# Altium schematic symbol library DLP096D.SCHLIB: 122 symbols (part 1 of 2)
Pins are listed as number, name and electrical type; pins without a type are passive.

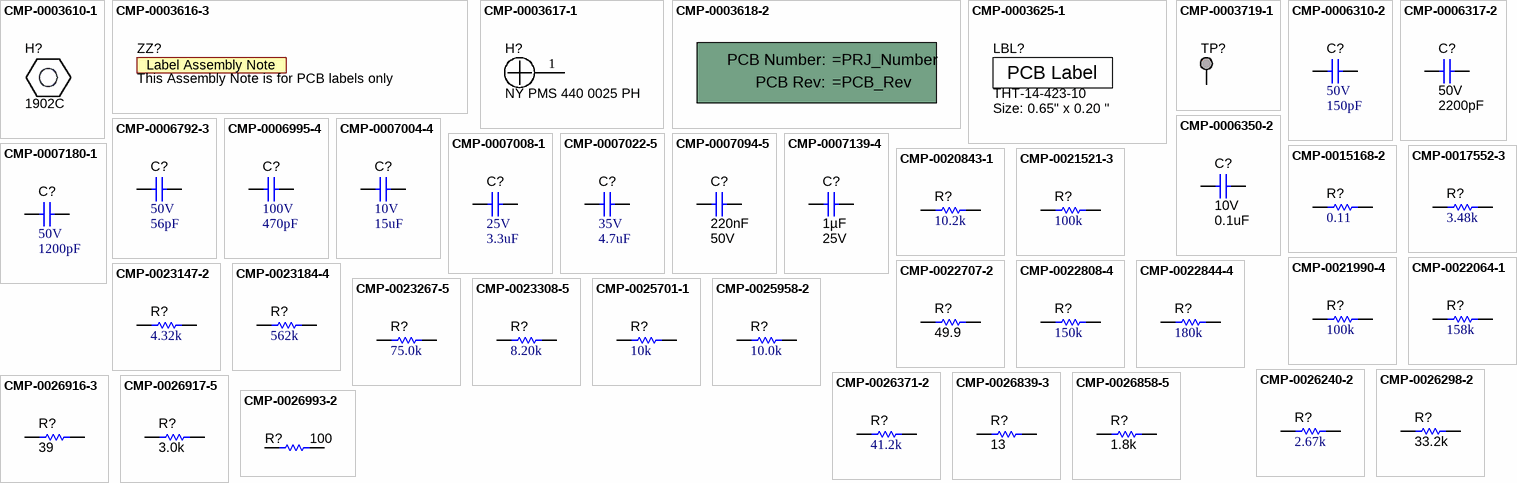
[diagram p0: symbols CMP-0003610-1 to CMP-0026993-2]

## CMP-0003610-1
designator H?, comment 1902C
Standoff, Hex, 0.5"L #4-40 Nylon; Manufacturer: Keystone; CompType: Hardware
footprint Keystone_1902C (Hex Standoff, 4-40 threaded, nylon)

## CMP-0003616-3
designator ZZ?, comment This Assembly Note is for PCB labels only  (no BOM)
Key: AssemblyNoteLabel
footprint AssemblyNoteLabel (Assembly Note for PCB Labels)

## CMP-0003617-1
designator H?, comment NY PMS 440 0025 PH
Machine Screw, Round, #4-40 x 1/4, Nylon, Philips panhead; Manufacturer: B&F Fastener Supply; CompType: Hardware
footprint NY PMS 440 0025 PH (4-40 nylon screw and mounting hole)
footprint NY PMS 440 0025 PH_3Donly (4-40 nylon screw)
pins: 1

## CMP-0003618-2
designator !PCB?, comment Printed Circuit Board  (value not drawn)  (mechanical)
Manufacturer: Any; CompType: PCB
1 alternate drawing of the same symbol

## CMP-0003625-1
designator LBL?, comment THT-14-423-10  Note: Size: 0.65" x 0.20 "
Thermal Transfer Printable Labels, 0.650" W x 0.200" H - 10,000 per roll; Manufacturer: Brady; CompType: Label
footprint Label_650x200 (Thermal Transfer Label)

## CMP-0003719-1
designator TP?, comment TP_H0.45P0.75  (value not drawn)  (no BOM)
Testpoint; Manufacturer: Texas Instruments; CompType: Pad
footprint TP_H045P075 (TP_H0.45P0.75)
pins: 1

## CMP-0006310-2
designator C?, comment VDC_V: 50V  ValueDisplayed: 150pF  (hidden comment: CGA2B2C0G1H151J050BA)
CAP, CERM, 150 pF, 50 V, +/- 5%, C0G/NP0, AEC-Q200 Grade 1, 0402; Manufacturer: TDK; TaMin_C: -55°C; Polarized: N; SizeAreaWB_mm2: 3; Value1: Unknown; U/M: EA; Value: 150pF; TaMax_C: 125°C; SizeZ_mm: 0.6; SizeX_mm: 1; SizeY_mm: 0.5; Cap_Case: 0402; CompType: Capacitor; AEC Qualified: Y; AEC Category: Q200
footprint 0402 (0402 from SM-752 data)
footprint 0402S (Based on C0402S footprint from PADS legacy)
footprint 0402L (0402 from SM-752 data)
footprint 0402M (0402 from SM-752 data)
pins: 1, 2

## CMP-0006317-2
designator C?, comment VDC_V: 50V  ValueDisplayed: 2200pF  (hidden comment: CGA2B2X7R1H222K050BA)
CAP, CERM, 2200 pF, 50 V, +/- 10%, X7R, AEC-Q200 Grade 1, 0402; Manufacturer: TDK; TaMin_C: -55°C; ESR_ohm: 1.07794; Polarized: N; SizeAreaWB_mm2: 3; Value1: 1.07794 ohm; U/M: EA; Value: 2200pF; TaMax_C: 125°C; SizeZ_mm: 0.6; SizeX_mm: 1; SizeY_mm: 0.5; Cap_Case: 0402; CompType: Capacitor; AEC Qualified: Y; Cap_F: 2.2nF; IRMS_A: 264.071mA; AEC Category: Q200
footprint 0402 (0402 from SM-752 data)
footprint 0402S (Based on C0402S footprint from PADS legacy)
footprint 0402L (0402 from SM-752 data)
footprint 0402M (0402 from SM-752 data)
pins: 1, 2

## CMP-0006350-2
designator C?, comment VDC_V: 10V  ValueDisplayed: 0.1uF  (hidden comment: GCM155R71A104KA55D)
CAP, CERM, 0.1 uF, 10 V, +/- 10%, X7R, AEC-Q200 Grade 1, 0402; Manufacturer: MuRata; TaMin_C: -55°C; Polarized: N; SizeAreaWB_mm2: 3; Value1: Unknown; U/M: EA; Value: 0.1uF; TaMax_C: 125°C; SizeZ_mm: 0.6; SizeX_mm: 1; SizeY_mm: 0.5; Cap_Case: 0402; CompType: Capacitor; AEC Qualified: Y; Cap_F: 100nF; AEC Category: Q200
footprint 0402 (0402 from SM-752 data)
footprint 0402S (Based on C0402S footprint from PADS legacy)
footprint 0402L (0402 from SM-752 data)
footprint 0402M (0402 from SM-752 data)
pins: 1, 2

## CMP-0006792-3
designator C?, comment VDC_V: 50V  ValueDisplayed: 56pF  (hidden comment: 06035A560FAT2A)
CAP, CERM, 56 pF, 50 V, +/- 1%, C0G/NP0, 0603; Manufacturer: AVX; TaMin_C: -55°C; Polarized: N; SizeAreaWB_mm2: 4.68; Value1: Unknown; U/M: EA; Value: 56pF; TaMax_C: 125°C; SizeZ_mm: 1; SizeX_mm: 1.6; SizeY_mm: 0.8; Cap_Case: 0603; SizeArea_mm2: 1.28; CompType: Capacitor; AEC Category: Q200
footprint 0603 (0603 from SM-752 data)
footprint 0603_HV (Ernesto recommended land pattern.  26 mil between pads.)
footprint 0603L (0603 from SM-752 data)
footprint 0603S
footprint 0603M (0603 from SM-752 data)
pins: 1, 2

## CMP-0006995-4
designator C?, comment VDC_V: 100V  ValueDisplayed: 470pF  (hidden comment: C1608C0G2A471J)
CAP, CERM, 470 pF, 100 V, +/- 5%, C0G/NP0, 0603; Manufacturer: TDK; TaMin_C: -55°C; ESR_ohm: 71.4m; Polarized: N; SizeAreaWB_mm2: 4.68; Value1: 0.0714 ohm; U/M: EA; Value: 470pF; TaMax_C: 125°C; SizeZ_mm: 1; SizeX_mm: 1.6; SizeY_mm: 0.8; Cap_Case: 0603; SizeArea_mm2: 1.28; CompType: Capacitor; AEC Category: Q200
footprint 0603 (0603 from SM-752 data)
footprint 0603_HV (Ernesto recommended land pattern.  26 mil between pads.)
footprint 0603L (0603 from SM-752 data)
footprint 0603S
footprint 0603M (0603 from SM-752 data)
pins: 1, 2

## CMP-0007004-4
designator C?, comment VDC_V: 10V  ValueDisplayed: 15uF  (hidden comment: C1608X5R1A156M080AC)
CAP, CERM, 15 uF, 10 V, +/- 20%, X5R, 0603; Manufacturer: TDK; TaMin_C: -55°C; ESR_ohm: 6.531m; Polarized: N; SizeAreaWB_mm2: 4.68; Value1: 0.006531 ohm; U/M: EA; Value: 15uF; TaMax_C: 85°C; SizeZ_mm: 1; SizeX_mm: 1.6; SizeY_mm: 0.8; Cap_Case: 0603; SizeArea_mm2: 1.28; CompType: Capacitor; Cap_F: 15µF; IRMS_A: 2.0344A; AEC Category: Q200
footprint 0603 (0603 from SM-752 data)
footprint 0603_HV (Ernesto recommended land pattern.  26 mil between pads.)
footprint 0603L (0603 from SM-752 data)
footprint 0603S
footprint 0603M (0603 from SM-752 data)
pins: 1, 2

## CMP-0007008-1
designator C?, comment VDC_V: 25V  ValueDisplayed: 3.3uF  (hidden comment: C1608X5R1E335K080AC)
CAP, CERM, 3.3 uF, 25 V, +/- 10%, X5R, 0603; Manufacturer: TDK; TaMin_C: -55°C; Polarized: N; SizeAreaWB_mm2: 4.68; Value1: Unknown; U/M: EA; Value: 3.3uF; TaMax_C: 85°C; SizeZ_mm: 1; SizeX_mm: 1.6; SizeY_mm: 0.8; Cap_Case: 0603; SizeArea_mm2: 1.28; CompType: Capacitor; Cap_F: 3.3µF; AEC Category: Q200
footprint 0603 (0603 from SM-752 data)
footprint 0603_HV (Ernesto recommended land pattern.  26 mil between pads.)
footprint 0603L (0603 from SM-752 data)
footprint 0603S
footprint 0603M (0603 from SM-752 data)
pins: 1, 2

## CMP-0007022-5
designator C?, comment VDC_V: 35V  ValueDisplayed: 4.7uF  (hidden comment: C1608X5R1V475K080AC)
CAP, CERM, 4.7 uF, 35 V, +/- 10%, X5R, 0603; Manufacturer: TDK; TaMin_C: -55°C; ESR_ohm: 3.728m; Polarized: N; SizeAreaWB_mm2: 4.68; Value1: 0.003728 ohm; U/M: EA; Value: 4.7uF; TaMax_C: 85°C; SizeZ_mm: 1; SizeX_mm: 1.6; SizeY_mm: 0.8; Cap_Case: 0603; SizeArea_mm2: 1.28; CompType: Capacitor; Cap_F: 4.7µF; IRMS_A: 2.6936A; AEC Category: Q200
footprint 0603 (0603 from SM-752 data)
footprint 0603_HV (Ernesto recommended land pattern.  26 mil between pads.)
footprint 0603L (0603 from SM-752 data)
footprint 0603S
footprint 0603M (0603 from SM-752 data)
pins: 1, 2

## CMP-0007094-5
designator C?, comment Cap_F: 220nF  VDC_V: 50V  (hidden comment: GCM188R71E104KA57D)
CAP, CERM, 0.22 uF, 50 V, +/- 10%, X7R, AEC-Q200 Grade 1, 0603; Manufacturer: TDK; PartNumber: CGA3E3X7R1H224K080AB; TaMin_C: -55°C; ESR_ohm: 0.021699; Polarized: N; SizeAreaWB_mm2: 4.68; Value1: 0.021699 ohm; U/M: EA; Value: 0.22uF; TaMax_C: 125°C; SizeZ_mm: 1; SizeX_mm: 1.6; SizeY_mm: 0.8; Cap_Case: 0603; SizeArea_mm2: 1.28; CompType: Capacitor; AEC Qualified: Y; IRMS_A: 1.12496A; AEC Category: Q200
footprint 0603 (0603 from SM-752 data)
footprint 0603_HV (Ernesto recommended land pattern.  26 mil between pads.)
footprint 0603L (0603 from SM-752 data)
footprint 0603S
footprint 0603M (0603 from SM-752 data)
pins: 1, 2

## CMP-0007139-4
designator C?, comment Cap_F: 1µF  VDC_V: 25V  (hidden comment: GCM188R71E105KA64D)
CAP, CERM, 1 uF, 25 V, +/- 10%, X7R, AEC-Q200 Grade 1, 0603; Manufacturer: MuRata; TaMin_C: -55°C; Polarized: N; SizeAreaWB_mm2: 4.68; Value1: Unknown; U/M: EA; Value: 1uF; TaMax_C: 125°C; SizeZ_mm: 1; SizeX_mm: 1.6; SizeY_mm: 0.8; Cap_Case: 0603; SizeArea_mm2: 1.28; CompType: Capacitor; AEC Qualified: Y; AEC Category: Q200
footprint 0603 (0603 from SM-752 data)
footprint 0603_HV (Ernesto recommended land pattern.  26 mil between pads.)
footprint 0603L (0603 from SM-752 data)
footprint 0603S
footprint 0603M (0603 from SM-752 data)
pins: 1, 2

## CMP-0007180-1
designator C?, comment VDC_V: 50V  ValueDisplayed: 1200pF  (hidden comment: GRM1885C1H122JA01D)
CAP, CERM, 1200 pF, 50 V, +/- 5%, C0G/NP0, 0603; Manufacturer: MuRata; TaMin_C: -55°C; Polarized: N; SizeAreaWB_mm2: 4.68; Value1: Unknown; U/M: EA; Value: 1200pF; TaMax_C: 125°C; SizeZ_mm: 1; SizeX_mm: 1.6; SizeY_mm: 0.8; Cap_Case: 0603; SizeArea_mm2: 1.28; CompType: Capacitor; Cap_F: 1.2nF; AEC Category: Q200
footprint 0603 (0603 from SM-752 data)
footprint 0603_HV (Ernesto recommended land pattern.  26 mil between pads.)
footprint 0603L (0603 from SM-752 data)
footprint 0603S
footprint 0603M (0603 from SM-752 data)
pins: 1, 2

## CMP-0015168-2
designator R?, comment ValueDisplayed: 0.11  (hidden comment: MCR25JZHFLR110)
RES, 0.11, 1%, 0.5 W, 1210; Manufacturer: Rohm; Power_W: 500mW; TempCo: 200 ppm/C; SizeAreaWB_mm2: 14.7; Value_Code: R110; U/M: EA; Value: 0.11; EIA_Code: E96; SizeX_mm: 3.2; SizeY_mm: 2.5; SizeZ_mm: 1.35; Value2: 0.5W; SizeArea_mm2: 8; CompType: Resistor; VDC_V: 0V; AEC Category: Q200
footprint 1210 (1210 from SM-752 data)
footprint 1210L (1210 from SM-752 data)
footprint 1210M (1210 from SM-752 data)
pins: 1, 2

## CMP-0017552-3
designator R?, comment ValueDisplayed: 3.48k  (hidden comment: ERJ-8ENF3481V)
RES, 3.48 k, 1%, 0.25 W, AEC-Q200 Grade 0, 1206; Manufacturer: Panasonic; Power_W: 250mW; TempCo: 100 ppm/C; Value_Code: 3k48; Value: 3.48k; EIA_Code: E96; SizeX_mm: 3.2; SizeY_mm: 1.6; SizeZ_mm: 1.35; Value2: 0.25W; SizeArea_mm2: 5.12; CompType: Resistor; AEC Qualified: Y; VDC_V: 200V; AEC Category: Q200; AEC Grade: 0; SizeAreaWB_mm2: 10.92
footprint 1206 (1206 from SM-752 data)
footprint 1206M (1206 from SM-752 data)
footprint 1206L (1206 from SM-752 data)
pins: 1, 2

## CMP-0020843-1
designator R?, comment ValueDisplayed: 10.2k  (hidden comment: CRCW080510K2FKEA)
RES, 10.2 k, 1%, 0.125 W, 0805; Manufacturer: Vishay-Dale; Power_W: 125mW; TempCo: 100 ppm/C; Value_Code: 10k2; U/M: EA; Value: 10.2k; EIA_Code: E96; SizeX_mm: 2; SizeY_mm: 1.25; SizeZ_mm: 1.45; Value2: 0.125W; SizeArea_mm2: 2.5; CompType: Resistor; VDC_V: 150V; AEC Category: Q200
footprint 0805_HV (0805 with 30mil clearance between pads)
footprint 0805M (0805 from SM-752 data)
footprint 0805 (0805 from SM-752 data)
footprint 0805L (0805 from SM-752 data)
footprint 0805_HV1 (Custom footprint based on analyzing multiple manufacturer recommendations)
pins: 1, 2

## CMP-0021521-3
designator R?, comment ValueDisplayed: 100k  (hidden comment: ERJ-6ENF1003V)
RES, 100 k, 1%, 0.125 W, AEC-Q200 Grade 0, 0805; Manufacturer: Panasonic; Power_W: 125mW; TempCo: 100 ppm/C; Value: 100k; EIA_Code: E96; SizeX_mm: 2; SizeY_mm: 1.25; SizeZ_mm: 1.45; Value2: 0.125W; SizeArea_mm2: 2.5; CompType: Resistor; AEC Qualified: Y; AEC Category: Q200; AEC Grade: 0; SizeAreaWB_mm2: 6.75
footprint 0805_HV (0805 with 30mil clearance between pads)
footprint 0805_HV1 (Custom footprint based on analyzing multiple manufacturer recommendations)
footprint 0805 (0805 from SM-752 data)
footprint 0805M (0805 from SM-752 data)
footprint 0805L (0805 from SM-752 data)
pins: 1, 2

## CMP-0021990-4
designator R?, comment ValueDisplayed: 100k  (hidden comment: CRCW0603100KFKEA)
RES, 100 k, 1%, 0.1 W, AEC-Q200 Grade 0, 0603; Manufacturer: Vishay-Dale; Power_W: 100mW; TempCo: 100 ppm/C; Value: 100k; EIA_Code: E96; SizeX_mm: 1.6; SizeY_mm: 0.8; SizeZ_mm: 1; Value2: 0.1W; SizeArea_mm2: 1.28; CompType: Resistor; AEC Qualified: Y; VDC_V: 75V; AEC Category: Q200; AEC Grade: 0
footprint 0603 (0603 from SM-752 data)
footprint 0603_HV (Ernesto recommended land pattern.  26 mil between pads.)
footprint 0603L (0603 from SM-752 data)
footprint 0603S
footprint 0603M (0603 from SM-752 data)
pins: 1, 2

## CMP-0022064-1
designator R?, comment ValueDisplayed: 158k  (hidden comment: CRCW0603158KFKEA)
RES, 158 k, 1%, 0.1 W, 0603; Manufacturer: Vishay-Dale; Power_W: 100mW; TempCo: 100 ppm/C; U/M: EA; Value: 158k; EIA_Code: E96; SizeX_mm: 1.6; SizeY_mm: 0.8; SizeZ_mm: 1; Value2: 0.1W; SizeArea_mm2: 1.28; CompType: Resistor; VDC_V: 75V; AEC Category: Q200
footprint 0603 (0603 from SM-752 data)
footprint 0603_HV (Ernesto recommended land pattern.  26 mil between pads.)
footprint 0603L (0603 from SM-752 data)
footprint 0603S
footprint 0603M (0603 from SM-752 data)
pins: 1, 2

## CMP-0022707-2
designator R?, comment ValueDisplayed: 49.9  (hidden comment: ERJ-3EKF49R9V)
RES, 49.9, 1%, 0.1 W, AEC-Q200 Grade 0, 0603; Manufacturer: Panasonic; Power_W: 100mW; Value_Code: 49R9; U/M: EA; Value: 49.9; EIA_Code: E96; TempCo: 100 ppm/C; SizeX_mm: 1.6; SizeY_mm: 0.8; SizeZ_mm: 1; Value2: 0.1W; SizeArea_mm2: 1.28; CompType: Resistor; AEC Qualified: Y; AEC Grade: 0; AEC Category: Q200
footprint 0603 (0603 from SM-752 data)
footprint 0603_HV (Ernesto recommended land pattern.  26 mil between pads.)
footprint 0603L (0603 from SM-752 data)
footprint 0603S
footprint 0603M (0603 from SM-752 data)
pins: 1, 2

## CMP-0022808-4
designator R?, comment ValueDisplayed: 150k  (hidden comment: RC0603FR-07150KL)
RES, 150 k, 1%, 0.1 W, 0603; Manufacturer: Yageo; Power_W: 100mW; TempCo: 100 ppm/C; Value: 150k; EIA_Code: E96; SizeX_mm: 1.6; SizeY_mm: 0.8; SizeZ_mm: 1; Value2: 0.1W; SizeArea_mm2: 1.28; CompType: Resistor; AEC Qualified: N; VDC_V: 75V; AEC Category: Q200; SizeAreaWB_mm2: 4.68
footprint 0603 (0603 from SM-752 data)
footprint 0603_HV (Ernesto recommended land pattern.  26 mil between pads.)
footprint 0603L (0603 from SM-752 data)
footprint 0603S
footprint 0603M (0603 from SM-752 data)
pins: 1, 2

## CMP-0022844-4
designator R?, comment ValueDisplayed: 180k  (hidden comment: RC0603FR-07180KL)
RES, 180 k, 1%, 0.1 W, 0603; Manufacturer: Yageo; Power_W: 100mW; TempCo: 100 ppm/C; Value: 180k; SizeX_mm: 1.6; SizeY_mm: 0.8; SizeZ_mm: 1; Value2: 0.1W; SizeArea_mm2: 1.28; CompType: Resistor; AEC Qualified: N; VDC_V: 75V; AEC Category: Q200; SizeAreaWB_mm2: 4.68
footprint 0603 (0603 from SM-752 data)
footprint 0603_HV (Ernesto recommended land pattern.  26 mil between pads.)
footprint 0603L (0603 from SM-752 data)
footprint 0603S
footprint 0603M (0603 from SM-752 data)
pins: 1, 2

## CMP-0023147-2
designator R?, comment ValueDisplayed: 4.32k  (hidden comment: RC0603FR-074K32L)
RES, 4.32 k, 1%, 0.1 W, 0603; Manufacturer: Yageo America; Power_W: 100mW; TempCo: 200 ppm/C; Value_Code: 4k32; U/M: EA; Value: 4.32k; EIA_Code: E96; SizeX_mm: 1.6; SizeY_mm: 0.8; SizeZ_mm: 1; Value2: 0.1W; SizeArea_mm2: 1.28; CompType: Resistor; VDC_V: 150V; AEC Category: Q200
footprint 0603 (0603 from SM-752 data)
footprint 0603_HV (Ernesto recommended land pattern.  26 mil between pads.)
footprint 0603L (0603 from SM-752 data)
footprint 0603S
footprint 0603M (0603 from SM-752 data)
pins: 1, 2

## CMP-0023184-4
designator R?, comment ValueDisplayed: 562k  (hidden comment: RC0603FR-07562KL)
RES, 562 k, 1%, 0.1 W, 0603; Manufacturer: Yageo; Power_W: 100mW; TempCo: 100 ppm/C; Value: 562k; EIA_Code: E96; SizeX_mm: 1.6; SizeY_mm: 0.8; SizeZ_mm: 1; Value2: 0.1W; SizeArea_mm2: 1.28; CompType: Resistor; AEC Qualified: N; VDC_V: 75V; AEC Category: Q200; SizeAreaWB_mm2: 4.68
footprint 0603 (0603 from SM-752 data)
footprint 0603_HV (Ernesto recommended land pattern.  26 mil between pads.)
footprint 0603L (0603 from SM-752 data)
footprint 0603S
footprint 0603M (0603 from SM-752 data)
pins: 1, 2

## CMP-0023267-5
designator R?, comment ValueDisplayed: 75.0k  (hidden comment: RC0603FR-0775KL)
RES, 75.0 k, 1%, 0.1 W, 0603; Manufacturer: Yageo; Power_W: 100mW; TempCo: 100 ppm/C; Value_Code: 75k0; Value: 75.0k; EIA_Code: E96; Res_ohm: 75k; SizeX_mm: 1.6; SizeY_mm: 0.8; SizeZ_mm: 1; Value2: 0.1W; SizeArea_mm2: 1.28; CompType: Resistor; AEC Qualified: N; VDC_V: 75V; AEC Category: Q200; SizeAreaWB_mm2: 4.68
footprint 0603 (0603 from SM-752 data)
footprint 0603_HV (Ernesto recommended land pattern.  26 mil between pads.)
footprint 0603L (0603 from SM-752 data)
footprint 0603S
footprint 0603M (0603 from SM-752 data)
pins: 1, 2

## CMP-0023308-5
designator R?, comment ValueDisplayed: 8.20k  (hidden comment: RC0603FR-078K2L)
RES, 8.20 k, 1%, 0.1 W, 0603; Manufacturer: Yageo; Power_W: 100mW; TempCo: 100 ppm/C; Value_Code: 8k20; Value: 8.20k; Res_ohm: 8.2k; SizeX_mm: 1.6; SizeY_mm: 0.8; SizeZ_mm: 1; Value2: 0.1W; SizeArea_mm2: 1.28; CompType: Resistor; AEC Qualified: N; VDC_V: 75V; AEC Category: Q200; SizeAreaWB_mm2: 4.68
footprint 0603 (0603 from SM-752 data)
footprint 0603_HV (Ernesto recommended land pattern.  26 mil between pads.)
footprint 0603L (0603 from SM-752 data)
footprint 0603S
footprint 0603M (0603 from SM-752 data)
pins: 1, 2

## CMP-0025701-1
designator R?, comment ValueDisplayed: 10k  (hidden comment: CRCW060310K0JNEA)
RES, 10 k, 5%, 0.1 W, 0603; Manufacturer: Vishay-Dale; Power_W: 100mW; TempCo: 200 ppm/C; Value_Code: 10k0; U/M: EA; Value: 10k; EIA_Code: E24; SizeX_mm: 1.6; SizeY_mm: 0.8; SizeZ_mm: 1; Value2: 0.1W; SizeArea_mm2: 1.28; CompType: Resistor; VDC_V: 75V; AEC Category: Q200
footprint 0603 (0603 from SM-752 data)
footprint 0603_HV (Ernesto recommended land pattern.  26 mil between pads.)
footprint 0603L (0603 from SM-752 data)
footprint 0603S
footprint 0603M (0603 from SM-752 data)
pins: 1, 2

## CMP-0025958-2
designator R?, comment ValueDisplayed: 10.0k  (hidden comment: CRCW040210K0FKED)
RES, 10.0 k, 1%, 0.063 W, 0402; Manufacturer: Vishay-Dale; Power_W: 63mW; TempCo: 100 ppm/C; Value_Code: 10k0; U/M: EA; Value: 10.0k; EIA_Code: E96; Res_ohm: 10k; SizeX_mm: 1; SizeY_mm: 0.5; SizeZ_mm: 0.6; Value2: 0.063W; CompType: Resistor; VDC_V: 50V; AEC Category: Q200
footprint 0402 (0402 from SM-752 data)
footprint 0402S (Based on C0402S footprint from PADS legacy)
footprint 0402L (0402 from SM-752 data)
footprint 0402M (0402 from SM-752 data)
pins: 1, 2

## CMP-0026240-2
designator R?, comment ValueDisplayed: 2.67k  (hidden comment: CRCW04022K67FKED)
RES, 2.67 k, 1%, 0.063 W, AEC-Q200 Grade 0, 0402; Manufacturer: Vishay-Dale; Power_W: 63mW; TempCo: 100 ppm/C; Value_Code: 2k67; Value: 2.67k; EIA_Code: E96; SizeX_mm: 1; SizeY_mm: 0.5; SizeZ_mm: 0.6; Value2: 0.063W; CompType: Resistor; AEC Qualified: Y; VDC_V: 50V; AEC Category: Q200; AEC Grade: 0
footprint 0402 (0402 from SM-752 data)
footprint 0402S (Based on C0402S footprint from PADS legacy)
footprint 0402L (0402 from SM-752 data)
footprint 0402M (0402 from SM-752 data)
pins: 1, 2

## CMP-0026298-2
designator R?, comment ValueDisplayed: 33.2k  (hidden comment: CRCW040233K2FKED)
RES, 33.2 k, 1%, 0.063 W, AEC-Q200 Grade 0, 0402; Manufacturer: Vishay-Dale; Power_W: 63mW; TempCo: 100 ppm/C; Value_Code: 33k2; Value: 33.2k; EIA_Code: E96; SizeX_mm: 1; SizeY_mm: 0.5; SizeZ_mm: 0.6; Value2: 0.063W; CompType: Resistor; AEC Qualified: Y; VDC_V: 50V; AEC Category: Q200; AEC Grade: 0
footprint 0402 (0402 from SM-752 data)
footprint 0402S (Based on C0402S footprint from PADS legacy)
footprint 0402L (0402 from SM-752 data)
footprint 0402M (0402 from SM-752 data)
pins: 1, 2

## CMP-0026371-2
designator R?, comment ValueDisplayed: 41.2k  (hidden comment: CRCW040241K2FKED)
RES, 41.2 k, 1%, 0.063 W, AEC-Q200 Grade 0, 0402; Manufacturer: Vishay-Dale; Power_W: 63mW; TempCo: 100 ppm/C; Value_Code: 41k2; Value: 41.2k; EIA_Code: E96; SizeX_mm: 1; SizeY_mm: 0.5; SizeZ_mm: 0.6; Value2: 0.063W; CompType: Resistor; AEC Qualified: Y; VDC_V: 50V; AEC Category: Q200; AEC Grade: 0
footprint 0402 (0402 from SM-752 data)
footprint 0402S (Based on C0402S footprint from PADS legacy)
footprint 0402L (0402 from SM-752 data)
footprint 0402M (0402 from SM-752 data)
pins: 1, 2

## CMP-0026839-3
designator R?, comment ValueDisplayed: 13  (hidden comment: CRCW040213R0JNED)
RES, 13, 5%, 0.063 W, AEC-Q200 Grade 0, 0402; Manufacturer: Vishay-Dale; Power_W: 63mW; TempCo: 200 ppm/C; Value_Code: 13R0; Value: 13; EIA_Code: E24; SizeX_mm: 1; SizeY_mm: 0.5; SizeZ_mm: 0.6; Value2: 0.063W; CompType: Resistor; AEC Qualified: Y; VDC_V: 50V; AEC Category: Q200; AEC Grade: 0
footprint 0402 (0402 from SM-752 data)
footprint 0402S (Based on C0402S footprint from PADS legacy)
footprint 0402L (0402 from SM-752 data)
footprint 0402M (0402 from SM-752 data)
pins: 1, 2

## CMP-0026858-5
designator R?, comment ValueDisplayed: 1.8k  (hidden comment: CRCW04021K80JNED)
RES, 1.8 k, 5%, 0.063 W, AEC-Q200 Grade 0, 0402; Manufacturer: Vishay-Dale; Power_W: 63mW; TempCo: 200 ppm/C; Value_Code: 1k80; Value: 1.8k; EIA_Code: E24; SizeX_mm: 1; SizeY_mm: 0.5; SizeZ_mm: 0.6; Value2: 0.063W; CompType: Resistor; AEC Qualified: Y; VDC_V: 50V; AEC Category: Q200; AEC Grade: 0
footprint 0402 (0402 from SM-752 data)
footprint 0402S (Based on C0402S footprint from PADS legacy)
footprint 0402L (0402 from SM-752 data)
footprint 0402M (0402 from SM-752 data)
pins: 1, 2

## CMP-0026916-3
designator R?, comment ValueDisplayed: 39  (hidden comment: CRCW040239R0JNED)
RES, 39, 5%, 0.063 W, AEC-Q200 Grade 0, 0402; Manufacturer: Vishay-Dale; Power_W: 63mW; TempCo: 200 ppm/C; Value_Code: 39R0; Value: 39; EIA_Code: E24; SizeX_mm: 1; SizeY_mm: 0.5; SizeZ_mm: 0.6; Value2: 0.063W; CompType: Resistor; AEC Qualified: Y; VDC_V: 50V; AEC Category: Q200; AEC Grade: 0
footprint 0402 (0402 from SM-752 data)
footprint 0402S (Based on C0402S footprint from PADS legacy)
footprint 0402L (0402 from SM-752 data)
footprint 0402M (0402 from SM-752 data)
pins: 1, 2

## CMP-0026917-5
designator R?, comment ValueDisplayed: 3.0k  (hidden comment: CRCW04023K00JNED)
RES, 3.0 k, 5%, 0.063 W, AEC-Q200 Grade 0, 0402; Manufacturer: Vishay-Dale; Power_W: 63mW; TempCo: 200 ppm/C; Value_Code: 3k00; Value: 3.0k; EIA_Code: E24; Res_ohm: 3k; SizeX_mm: 1; SizeY_mm: 0.5; SizeZ_mm: 0.6; Value2: 0.063W; CompType: Resistor; AEC Qualified: Y; VDC_V: 50V; AEC Category: Q200; AEC Grade: 0
footprint 0402 (0402 from SM-752 data)
footprint 0402S (Based on C0402S footprint from PADS legacy)
footprint 0402L (0402 from SM-752 data)
footprint 0402M (0402 from SM-752 data)
pins: 1, 2

## CMP-0026993-2
designator R?, comment ValueDisplayed: 100  (hidden comment: ERJ-2GEJ101X)
RES, 100, 5%, 0.1 W, AEC-Q200 Grade 0, 0402; Manufacturer: Panasonic; Power_W: 100mW; TempCo: 200 ppm/C; Value_Code: 100R; U/M: EA; Value: 100; EIA_Code: E24; SizeX_mm: 1; SizeY_mm: 0.5; SizeZ_mm: 0.6; Value2: 0.1W; CompType: Resistor; AEC Qualified: Y; AEC Grade: 0; AEC Category: Q200
footprint 0402 (0402 from SM-752 data)
footprint 0402S (Based on C0402S footprint from PADS legacy)
footprint 0402L (0402 from SM-752 data)
footprint 0402M (0402 from SM-752 data)
pins: 1, 2

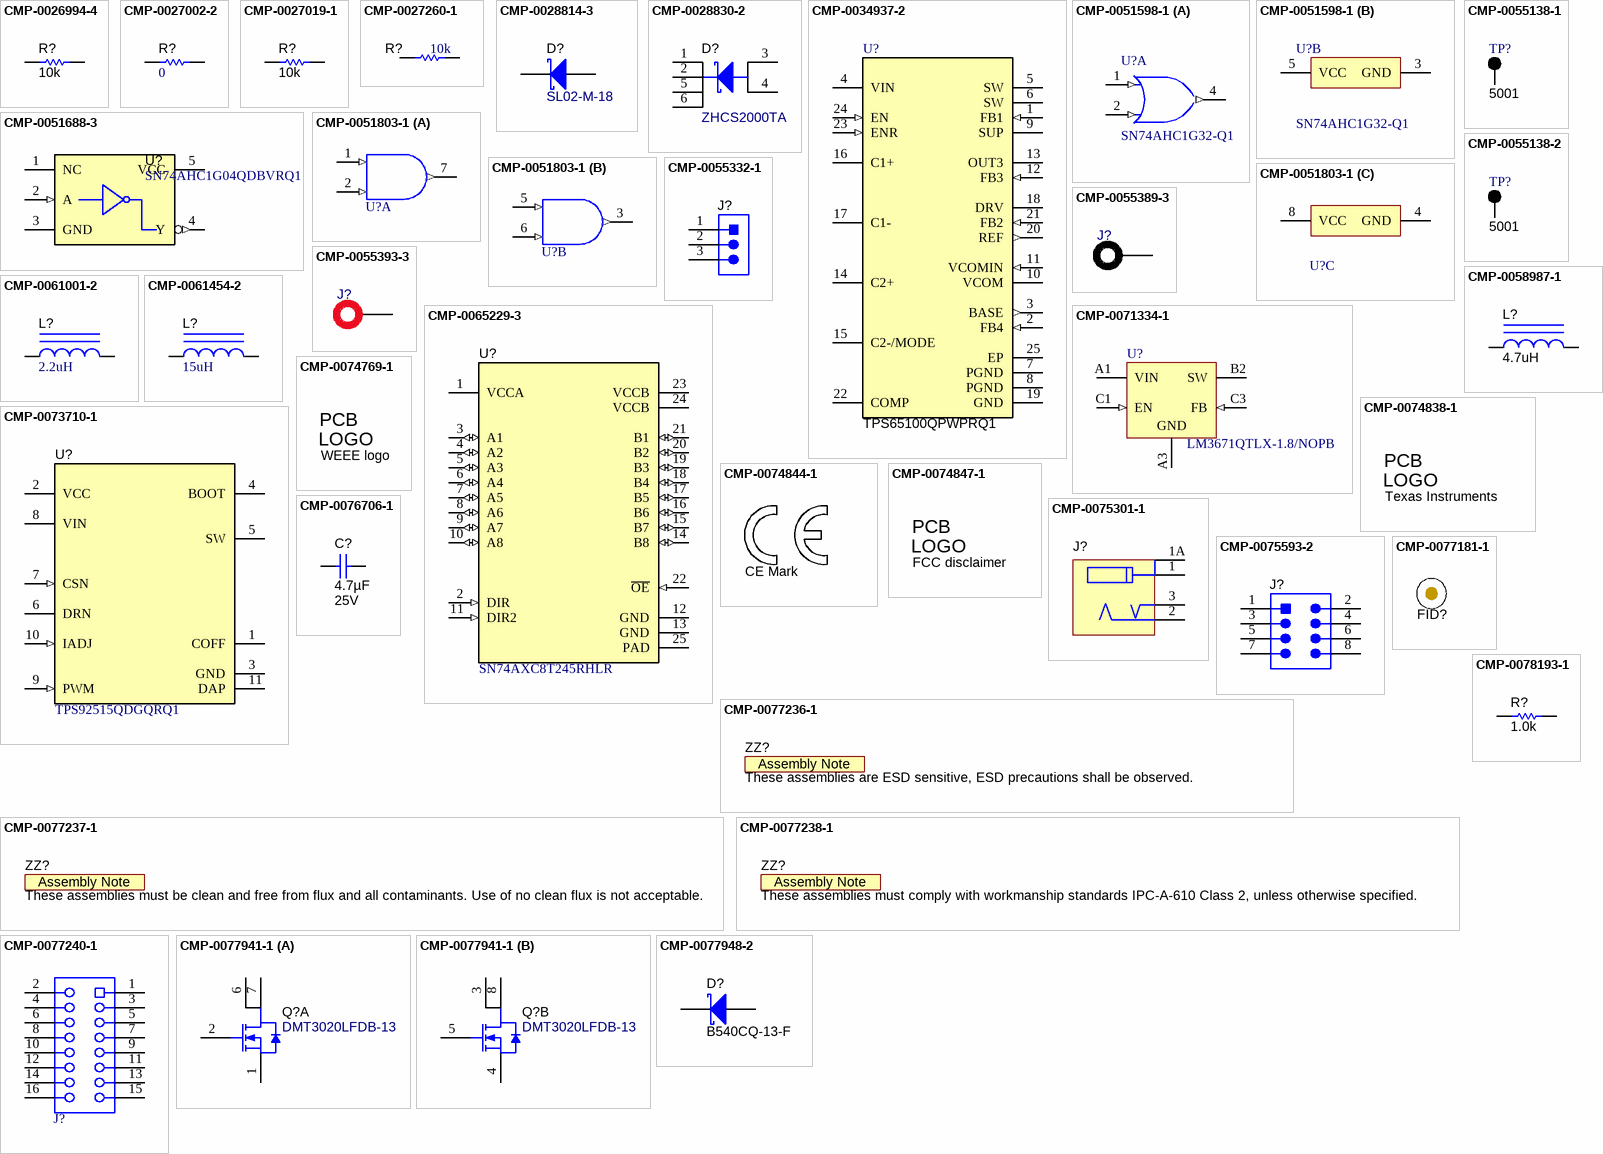
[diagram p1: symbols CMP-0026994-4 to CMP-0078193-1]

## CMP-0026994-4
designator R?, comment ValueDisplayed: 10k  (hidden comment: ERJ-2GEJ103X)
RES, 10 k, 5%, 0.1 W, AEC-Q200 Grade 0, 0402; Manufacturer: Panasonic; Power_W: 100mW; TempCo: 200 ppm/C; Value_Code: 10k0; U/M: EA; Value: 10k; EIA_Code: E24; SizeX_mm: 1; SizeY_mm: 0.5; SizeZ_mm: 0.6; Value2: 0.1W; CompType: Resistor; AEC Qualified: Y; VDC_V: 50V; AEC Grade: 0; AEC Category: Q200
footprint 0402 (0402 from SM-752 data)
footprint 0402S (Based on C0402S footprint from PADS legacy)
footprint 0402L (0402 from SM-752 data)
footprint 0402M (0402 from SM-752 data)
pins: 1, 2

## CMP-0027002-2
designator R?, comment ValueDisplayed: 0  (hidden comment: MCR01MZPJ000)
RES, 0, 5%, 0.063 W, 0402; Manufacturer: Rohm; Power_W: 63mW; TempCo: 500 ppm/C; Value_Code: 0000; U/M: EA; Value: 0; EIA_Code: E24; SizeX_mm: 1; SizeY_mm: 0.5; SizeZ_mm: 0.6; Value2: 0.063W; CompType: Resistor; VDC_V: 50V; AEC Category: Q200
footprint 0402 (0402 from SM-752 data)
footprint 0402S (Based on C0402S footprint from PADS legacy)
footprint 0402L (0402 from SM-752 data)
footprint 0402M (0402 from SM-752 data)
pins: 1, 2

## CMP-0027019-1
designator R?, comment ValueDisplayed: 10k  (hidden comment: RC0201JR-0710KL)
RES, 10 k, 5%, 0.05 W, 0201; Manufacturer: Yageo America; Power_W: 50mW; TempCo: 200 ppm/C; Value_Code: 10k0; U/M: EA; Value: 10k; EIA_Code: E24; SizeX_mm: 0.6; SizeY_mm: 0.3; SizeZ_mm: 0.26; Value2: 0.05W; SizeArea_mm2: 0.18; CompType: Resistor; AEC Qualified: N; VDC_V: 25V; AEC Category: Q200
footprint 0201 (Data from Kemet datasheet CC101_COM dated 7/28/11)
footprint 0201_Silk (Data from Kemet datasheet CC101_COM dated 7/28/11)
footprint 0201L (Data from Kemet datasheet CC101_COM dated 7/28/11)
footprint 0201M (Data from Kemet datasheet CC101_COM dated 7/28/11)
pins: 1, 2

## CMP-0027260-1
designator R?, comment ValueDisplayed: 10k  (hidden comment: RC0201JS-7D10KL)
RES, 10 k, 5%, 0.05 W, 0201; Manufacturer: Yageo America; Power_W: 50mW; TempCo: 200 ppm/C; Value_Code: 10k0; U/M: EA; Value: 10k; EIA_Code: E24; SizeX_mm: 0.6; SizeY_mm: 0.3; SizeZ_mm: 0.26; Value2: 0.05W; SizeArea_mm2: 0.18; CompType: Resistor; AEC Qualified: N; VDC_V: 25V; AEC Category: Q200
footprint 0201 (Data from Kemet datasheet CC101_COM dated 7/28/11)
footprint 0201_Silk (Data from Kemet datasheet CC101_COM dated 7/28/11)
footprint 0201L (Data from Kemet datasheet CC101_COM dated 7/28/11)
footprint 0201M (Data from Kemet datasheet CC101_COM dated 7/28/11)
pins: 1, 2

## CMP-0028814-3
designator D?, comment SL02-M-18
Diode, Schottky, 20 V, 1.1 A, AEC-Q101, DO-219AB; Manufacturer: Vishay-Semiconductor; Io_A: 1.1A; Green_Lifecycle: Not Set; SizeAreaWB_mm2: 13.16; Vr_V: 20V; Green_REACh: Incomplete; TJmax_C: 125°C; Value: 20V; SizeZ_mm: 1.08; SizeX_mm: 3.7; SizeY_mm: 1.8; Vf_V: 420mV; Value2: 0.42V; SizeArea_mm2: 6.66; AEC Qualified: Y; AEC Category: Q101
footprint DO-219AB (Vishay Semiconductor)
pins: 1 K, 2 A

## CMP-0028830-2
designator D?, comment ZHCS2000TA
Diode, Schottky, 40 V, 2 A, AEC-Q101, SOT-26; Manufacturer: Diodes Inc.; SizeZ_mm: 1; Io_A: 2A; AEC Category: Q101; Vr_V: 40V; SizeY_mm: 2.8; Value2: 0.5V; TJmax_C: 125°C; SizeAreaWB_mm2: 13.68; Value: 40V; Green_REACh: Incomplete; AEC Qualified: Y; SizeX_mm: 2.6; SizeArea_mm2: 7.28; Vf_V: 500mV; Green_Lifecycle: Not Set
footprint SOT-26 (SOT23, 6-Leads, Body 3.1x3.0mm (max), Pitch 0.95mm, IPC Medium Density based on Diodes Inc ap02002.pdf rev 29)
pins: 1 K, 2 K, 3 A, 4 A, 5 K, 6 K

## CMP-0034937-2
designator U?, comment TPS65100QPWPRQ1
Dimmable Quasi-Resonant LED Lighting Controller, 9 to 21.5 V, -40 to 140 degC, 16-pin SOP (PW16), Green (RoHS & no Sb/Br); Manufacturer: Texas Instruments; SubFamily: LCD/OLED Display Bias Solutions; Rating: Automotive; Topology: Boost, Inverting Buck/Boost; Vin(Max)(V): 5.8; Vin(Min)(V): 2.7; Iout(Max)(A): 0.35; Iq(Typ)(mA): 0.75; Synchronous Rectification: TRUE; Switching Frequency(Typ)(kHz): 1600
footprint PWP0024B_N (TSOP, 24-Leads, Body 7.9x4.5mm (max), Pitch 0.65mm, IPC Medium Density)
footprint PWP0024B_M (TSOP, 24-Leads, Body 7.9x4.5mm (max), Pitch 0.65mm, IPC Low Density)
footprint PWP0024B_L (TSOP, 24-Leads, Body 7.9x4.5mm (max), Pitch 0.65mm, IPC High Density)
footprint PWP0024B_NV_N (TSOP, 24-Leads, Body 7.9x4.5mm (max), Pitch 0.65mm, IPC Medium Density)
footprint PWP0024B_NV_M (TSOP, 24-Leads, Body 7.9x4.5mm (max), Pitch 0.65mm, IPC Low Density)
footprint PWP0024B_NV_L (TSOP, 24-Leads, Body 7.9x4.5mm (max), Pitch 0.65mm, IPC High Density)
pins: 1 FB1 (in) "Feedback pin of the boost converter", 2 FB4 (in) "Feedback pin of the linear regulator controller. The linear regulator controller is set to a fixed output voltage of 3.3 V or 3 V depending on the version.", 3 BASE (out) "Base drive output for the external transistor", 4 VIN (power) "Input voltage pin of the device", 5 SW (power) "Switch pin of the boost converter", 6 SW (power) "Switch pin of the boost converter", 7 PGND (power) "Power ground", 8 PGND (power) "Power ground", 9 SUP (power) "Supply pin of the positive, negative charge pump, boost converter gate drive circuit, and VCOM buffer. This pin should be connected to the output of the main boost converter and cannot be connected to any other voltage (See Datasheet)", 10 VCOM (power) "VCOM buffer output", 11 VCOMIN (in) "Positive input terminal of the VCOM buffer. When the VCOM buffer is not used, this terminal can be connected to GND to reduce the overall quiescent current of the IC.", 12 FB3 (in) "Feedback pin of positive charge pump", 13 OUT3 (power) "Positive charge pump output", 14 C2+ "Positive terminal for the charge pump flying capacitor. If the device runs in voltage doubler mode, this pin should be left open.", 15 C2-/MODE "Negative terminal of the charge pump flying capacitor and charge pump MODE pin. If the flying capacitor is connected to this pin, the converter operates in a voltage tripler mode. If the charge pump needs to operate in a (See Datasheet)", 16 C1+ "Positive terminal of the charge pump flying capacitor", 17 C1- "Negative terminal of the charge pump flying capacitor", 18 DRV (power) "External charge pump driver", 19 GND (power) "Ground", 20 REF (out) "Internal reference output typically 1.23 V", 21 FB2 (in) "Feedback pin of negative charge pump", 22 COMP "Compensation pin for the main boost converter. A small capacitor is connected to this pin.", 23 ENR (in) "Enable pin of the linear regulator controller. This pin should be terminated and not be left floating. Logic high enables the regulator and a logic low puts the regulator in shutdown.", 24 EN (in) "Enable pin of the device. This pin should be terminated and not be left floating. A logic high enables the device and a logic low shuts down the device.", 25 EP (power) "The PowerPad or exposed thermal die needs to be connected to the power ground pins (PGND)"

## CMP-0051598-1
designator U?, comment Generic Part Number: SN74AHC1G32-Q1  (hidden comment: SN74AHC1G32TDBVRQ1)
Automotive Catalog Single 2-Input Positive-OR Gate, DBV0005A, LARGE T&R; Manufacturer: Texas Instruments; Output Type: CMOS; Bits(#): 1; Gate Type: OR; 3-State Output: No; VCC(Max)(V): 5.5; Voltage(Nom)(V): 3.3,5; Logic: True; tpd @ Nom Voltage(Max)(ns): 11.4,7.5; F @ Nom Voltage(Max)(Mhz): 75; Output Drive (IOL/IOH)(Max)(mA): 50/-50; Sub-Family: OR Gate; ICC @ Nom Voltage(Max)(mA): 0.01; Technology Family: AHC; VCC(Min)(V): 2
footprint DBV0005A_N (SOT23, 5-Leads, Body 2.9x1.6mm, Pitch 0.95mm, Lead Span 2.8mm, IPC Medium Density)
footprint DBV0005A_M (SOT23, 5-Leads, Body 2.9x1.6mm, Pitch 0.95mm, Lead Span 2.8mm, IPC Low Density)
footprint DBV0005A_L (SOT23, 5-Leads, Body 2.9x1.6mm, Pitch 0.95mm, Lead Span 2.8mm, IPC High Density)
part A pins: 1 A (in) "Input A", 2 B (in) "Input B", 4 Y (out) "Output Y"
part B pins: 3 GND (power) "Ground Pin", 5 VCC (power) "Power Pin"

## CMP-0051688-3
designator U?, comment SN74AHC1G04QDBVRQ1
Automotive Catalog Single Inverter Gate, DBV0005A (SOT-23-5); Manufacturer: Texas Instruments; Generic Part Number: SN74AHC1G04-Q1; Output Type: CMOS; tpd @ Nom Voltage(Max)(ns): 10.6,7.5; Bits(#): 1; Schmitt Trigger: No; VCC(Max)(V): 5.5; CompType: IC; Voltage(Nom)(V): 3.3,5; SizeAreaWB_mm2: 14.82; SizeX_mm: 2.8; ICC @ Nom Voltage(Max)(mA): 0.01; F @ Nom Voltage(Max)(Mhz): 75; SizeY_mm: 2.9; Logic: Inverting; AEC Category: Q200; Output Drive (IOL/IOH)(Max)(mA): 50/-50; SizeArea_mm2: 8.12; AEC Qualified: Y; SizeZ_mm: 1.45; VCC(Min)(V): 2
footprint DBV0005A_N (SOT23, 5-Leads, Body 2.9x1.6mm, Pitch 0.95mm, Lead Span 2.8mm, IPC Medium Density)
footprint DBV0005A_M (SOT23, 5-Leads, Body 2.9x1.6mm, Pitch 0.95mm, Lead Span 2.8mm, IPC Low Density)
footprint DBV0005A_L (SOT23, 5-Leads, Body 2.9x1.6mm, Pitch 0.95mm, Lead Span 2.8mm, IPC High Density)
pins: 1 NC, 2 A (in), 3 GND (power), 4 Y (out), 5 VCC (power)
2 alternate drawings of the same symbol

## CMP-0051803-1
designator U?, comment SN74LVC2G08IDCTRQ1  (value not drawn)
Automotive Catalog Dual 2-Input Positive-AND Gate, DCT0008A, LARGE T&R; Manufacturer: Texas Instruments; Generic Part Number: SN74LVC2G08-Q1; F @ Nom Voltage(Max)(Mhz): 150; ICC @ Nom Voltage(Max)(mA): 0.01; Input Type: CMOS/TTL; Output Type: CMOS; Logic: True; VCC(Max)(V): 5.5; Technology Family: LVC; Schmitt Trigger: No; Bits(#): 2; tpd @ Nom Voltage(Max)(ns): 9,5.1,4.7,3.8; VCC(Min)(V): 1.65; Voltage(Nom)(V): 1.8,2.5,3.3,5; Output Drive (IOL/IOH)(Max)(mA): 32/-32
footprint DCT0008A_N (TSOP, 8-Leads, Body 3x2.8mm, Pitch 0.65mm, IPC Medium Density)
footprint DCT0008A_M (TSOP, 8-Leads, Body 3x2.8mm, Pitch 0.65mm, IPC Low Density)
footprint DCT0008A_L (TSOP, 8-Leads, Body 3x2.8mm, Pitch 0.65mm, IPC High Density)
part A pins: 1 1A (in), 2 1B (in), 7 1Y (out)
part B pins: 3 2Y (out), 5 2A (in), 6 2B (in)
part C pins: 4 GND (power), 8 VCC (power)

## CMP-0055138-1
designator TP?, comment 5001
Test Point, Miniature, Black, TH; Manufacturer: Keystone; CNHeader: FALSE; Green_Lifecycle: Active; Green_REACh: Passed; ContactFinish: Silver; CT: TRUE
footprint Keystone5001 (For Keystone 500x miniature loop terminals)
pins: 1

## CMP-0055138-2
designator TP?, comment 5001
Test Point, Miniature, Black, TH; Manufacturer: Keystone Electronics; CNHeader: FALSE; Green_Lifecycle: Active; Green_REACh: Passed; ContactFinish: Silver; CT: TRUE
footprint Keystone5001 (For Keystone 500x miniature loop terminals)
pins: 1

## CMP-0055332-1
designator J?, comment 22284033  (value not drawn)
Header, 2.54mm, 3x1, Tin, TH; Manufacturer: Molex; CNHeader: TRUE; Current_A: 4A; Shrouded: N; Gender: Male; Voltage_V: 250V; Row_Count: 1; Pitch_mm: 2.54; CT: FALSE; Cert_UL: Y
footprint Molex_0022284033 (Header, 2.54mm, 3x1, TH)
pins: 1, 2, 3
3 alternate drawings of the same symbol

## CMP-0055389-3
designator J?, comment 571-0100  (value not drawn)
Standard Banana Jack, insulated, 10A, black; Manufacturer: DEM Manufacturing; Green_REACh: Incomplete; Green_Lifecycle: Not Set
footprint 571-0100 (Deltron Emcon recommended land pattern 2003-10-13)
footprint 571-0100_handsolder (Deltron Emcon recommended land pattern 2003-10-13)
footprint 571-0100_NS (Deltron Emcon recommended land pattern 2003-10-13)
pins: 1, 2

## CMP-0055393-3
designator J?, comment 571-0500  (value not drawn)
Standard Banana Jack, insulated, 10A, red; Manufacturer: DEM Manufacturing; Green_REACh: Incomplete; Green_Lifecycle: Not Set
footprint 571-0500 (Deltron Emcon recommended land pattern 2003-10-13)
footprint 571-0500_handsolder (Deltron Emcon recommended land pattern 2003-10-13)
footprint 571-0500_NS (Deltron Emcon recommended land pattern 2003-10-13)
pins: 1, 2

## CMP-0058987-1
designator L?, comment ValueDisplayed: 4.7uH  (hidden comment: FDSD0420D-4R7M)
Inductor, Shielded, 4.7 uH, 2.7 A, 0.083 ohm, AEC-Q200 Grade 1, SMD; Manufacturer: MuRata Toko; PartNumber: FDSD0420D-4R7M=P3; Isat: 2.7A @ 30% inductance drop; Irms: 3.6A @ 40C rise; SizeAreaWB_mm2: 27.04; DCR_ohm: 0.083; Value: 4.7uH; Imax_A: 2.7A; SizeZ_mm: 2; SizeX_mm: 4.2; SizeArea_mm2: 17.64; Ind_H: 4.7µH; AEC Qualified: Y; AEC Grade: 1; AEC Category: Q200
footprint FDSD0420 (SMD, 2-Leads, Body 4.2x4.2mm)
footprint FDSD0420_LessSilk (SMD, 2-Leads, Body 4.2x4.2mm)
pins: 1, 2

## CMP-0061001-2
designator L?, comment ValueDisplayed: 2.2uH  (hidden comment: XAL5030-222MEB)
Inductor, Shielded, Composite, 2.2 µH, 9.2 A, 0.01 ohm, AEC-Q200 Grade 1, SMD; Manufacturer: Coilcraft; Isat: 12.9A @ 30% inductance drop; Irms: 9.2A @ 40C rise; Green_Lifecycle: Not Set; SizeAreaWB_mm2: 54.4544; DCR_ohm: 10m; Green_REACh: Incomplete; Value: 2.2uH; Imax_A: 9.2A; SizeZ_mm: 3.1; SizeX_mm: 5.28; SizeY_mm: 5.48; SizeArea_mm2: 28.9344; Ind_H: 2.2µH; AEC Qualified: 1; AEC Category: Q200; AEC Grade: Y
footprint XAL5030 (Coilcraft XAL5030 12/12/11)
pins: 1, 2

## CMP-0061454-2
designator L?, comment ValueDisplayed: 15uH  (hidden comment: MSS1210-153ME)
Inductor, Shielded, Ferrite, 15 uH, 8.7 A, 0.019 ohm, SMD; Manufacturer: Coilcraft; Isat: 10.7A @ 30% inductance drop; Irms: 8.7A @ 40C rise; Green_Lifecycle: Not Set; SizeAreaWB_mm2: 204.49; DCR_ohm: 19m; Green_REACh: Incomplete; Value: 15uH; Imax_A: 8.7A; SizeZ_mm: 10; SizeX_mm: 12.3; SizeArea_mm2: 151.29; Ind_H: 15µH; AEC Category: Q200
footprint MSS1210 (Coilcraft MSS1210 series)
pins: 1, 2

## CMP-0065229-3
designator U?, comment SN74AXC8T245RHLR
Asynchronous Communication Between Data Buses, RHL0024A (VQFN-24); Manufacturer: Texas Instruments; Alternate PartNumber: SN74AXC8T245RHLT; SizeX_mm: 3.5; SizeY_mm: 5.5; CompType: IC; SizeZ_mm: 1.0; SizeArea_mm2: 19.25; SizeAreaWB_mm2: 41.25; AEC Category: Q200; AEC Qualified: N
footprint RHL0024A
pins: 1 VCCA (power), 2 DIR (in), 3 A1 (io), 4 A2 (io), 5 A3 (io), 6 A4 (io), 7 A5 (io), 8 A6 (io), 9 A7 (io), 10 A8 (io), 11 DIR2 (in), 12 GND (power), 13 GND (power), 14 B8 (io), 15 B7 (io), 16 B6 (io), 17 B5 (io), 18 B4 (io), 19 B3 (io), 20 B2 (io), 21 B1 (io), 22 ~{OE} (in), 23 VCCB (power), 24 VCCB (power), 25 PAD

## CMP-0071334-1
designator U?, comment PartNumber: LM3671QTLX-1.8/NOPB  (hidden comment: LM3671TLX-1.8/NOPB)
2MHz, 600mA Step-Down DC-DC Converter, 5-pin Micro SMD, Pb-Free; Manufacturer: Texas Instruments; High-Reliability: Y; PackageTopMarking: XV*I B; CompType: MiscPower
footprint YZR0005AEBA (Micro SMD, 5-Leads, Body 1.39x1.06mm, Pitch 0.5mm, NSC Recommended)
pins: A1 VIN (power), A3 GND (power), B2 SW (power), C1 EN (in), C3 FB (in)

## CMP-0073710-1
designator U?, comment TPS92515QDGQRQ1
2A LED Driver with Integrated NFET, High-Side Current Sense, and Shunt PWM Dimming Capable, DGQ0010E (VSSOP-10); Alternate PartNumber: TPS92515QDGQQ1; Alternate Manufacturer: Texas Instruments; Green_Lifecycle: Active; SizeAreaWB_mm2: 23.52; Green_REACh: Passed; U/M: EA; SizeZ_mm: 1.1; SizeX_mm: 4.88; SizeY_mm: 3.0; SizeArea_mm2: 14.64; CompType: IC
footprint DGQ0010E_N (TSSOP, 10-Leads, Body 3x3mm, Pitch 0.5mm, Thermal Pad 1.83x2.1mm, IPC Medium Density)
footprint DGQ0010E_L (TSSOP, 10-Leads, Body 3x3mm, Pitch 0.5mm, Thermal Pad 1.83x2.1mm, IPC High Density)
footprint DGQ0010E_M (TSSOP, 10-Leads, Body 3x3mm, Pitch 0.5mm, Thermal Pad 1.83x2.1mm, IPC Low Density)
pins: 1 COFF, 2 VCC (power), 3 GND (power), 4 BOOT (power), 5 SW (power), 6 DRN, 7 CSN (in), 8 VIN (power), 9 PWM (in), 10 IADJ (in), 11 DAP (power)
1 alternate drawing of the same symbol

## CMP-0074769-1
designator Logo?, comment WEEE logo  (no BOM)
footprint WEEE_Minimum (WEEElie bin)

## CMP-0074838-1
designator Logo?, comment Texas Instruments  (no BOM)
Texas Instrument Corporate Signature; SymbolCreator: a0412235; Lib Reference: TI_Logo; Library Reference: Logo
footprint TI_Horizontal_Overlay_Medium
footprint TI_Horizontal_Overlay_Small
footprint TI_Stacked_SolderMask_Small
footprint TI_Stacked_SolderMask_Small_Vertical
footprint TI_Symbol_Overlay_Medium
footprint TI_Symbol_Overlay_Small
footprint TI_Symbol_SolderMask_Medium
footprint TI_Symbol_SolderMask_Small
footprint TI_Horizontal_SolderMask_Medium
footprint TI_Horizontal_SolderMask_Small
footprint TI_Stacked_Overlay_Medium
footprint TI_Stacked_Overlay_Medium_Vertical
footprint TI_Stacked_Overlay_Small
footprint TI_Stacked_Overlay_Small_Vertical
footprint TI_Stacked_SolderMask_Medium
footprint TI_Stacked_SolderMask_Medium_Vertical

## CMP-0074844-1
designator Logo?, comment CE Mark  (no BOM)
SymbolCreator: a0412235
footprint CE_Mark_5mm (Minimum text height for CE Mark)
footprint CE_Mark_10mm (Double the minimum text height for CE Mark)

## CMP-0074847-1
designator Logo?, comment FCC disclaimer  (no BOM)
FCC_disclaimer; Library Reference: Logo
footprint FCC_disclaimer
footprint FCC_disclaimer_stacked

## CMP-0075301-1
designator J?, comment PJ-002BH-SMT-TR  (value not drawn)
Power Jack, 2.5x5.5mm, R/A, SMT; Manufacturer: CUI Inc.; CNHeader: False; Current_A: 5A; Gender: Female; Voltage_V: 24V; Row_Count: 2; RowSpacing_mm: 11.4; Pitch_mm: 6.1; ContactFinish: Silver; Cert_UL: Y
footprint CUI_PJ-002BH-SMT-TR (Power Jack, 4-Leads, Body 14.8x9mm, R/A, SMT)
pins: 1, 1A, 2, 3

## CMP-0075593-2
designator J?, comment TSM-104-01-L-DV  (value not drawn)
Header, 2.54mm, 4x2, Gold, SMT; Manufacturer: Samtec; Pitch_mm: 2.54; Gender: Male; Cert_CSA: Y; Green_REACh: Passed; Current_A: 4.9A; Voltage_V: 475V; Shrouded: N; Green_Lifecycle: Active; Row_Count: 2
footprint Samtec_TSM-104-01-x-DV (Header, 2.54mm, 4x2, SMT)
pins: 1, 2, 3, 4, 5, 6, 7, 8
1 alternate drawing of the same symbol

## CMP-0076706-1
designator C?, comment Cap_F: 4.7µF  VDC_V: 25V  (hidden comment: CGA4J1X7R1E475K125AC)
CAP, CERM, 4.7 µF, 25 V,+/- 10%, X7R, AEC-Q200 Grade 1, 0805; Manufacturer: TDK; SizeAreaWB_mm2: 6.75; SizeArea_mm2: 2.5; AEC Qualified: Y; AEC Category: Q200; Value: 4.7uF; TaMax_C: 125°C; SizeZ_mm: 1.45; AEC Grade: 1; Polarized: N; TaMin_C: -55°C; SizeY_mm: 1.25; U/M: EA; CompType: Capacitor; SizeX_mm: 2.0; Cap_Case: 2x1.25x1.25mm
footprint 0805L (0805 from SM-752 data)
footprint 0805M (0805 from SM-752 data)
footprint 0805 (0805 from SM-752 data)
footprint 0805_HV1 (Custom footprint based on analyzing multiple manufacturer recommendations)
footprint 0805_HV (0805 with 30mil clearance between pads)
pins: 1, 2

## CMP-0077181-1
designator FID?, comment Fiducial  (value not drawn)
Fiducial mark.  There is nothing to buy or mount.
footprint Fiducial10-30
footprint Fiducial15-30
footprint Fiducial10-20
footprint Fiducial20-40
footprint Fiducial6.4-20

## CMP-0077236-1
designator ZZ?, comment These assemblies are ESD sensitive, ESD precautions shall be observed.  (no BOM)
CompType: AssemblyNote
footprint AssemblyNote (Assembly Note)

## CMP-0077237-1
designator ZZ?, comment These assemblies must be clean and free from flux and all contaminants. Use of no clean flux is not acceptable.  (no BOM)
CompType: AssemblyNote
footprint AssemblyNote (Assembly Note)

## CMP-0077238-1
designator ZZ?, comment These assemblies must comply with workmanship standards IPC-A-610 Class 2, unless otherwise specified.  (no BOM)
CompType: AssemblyNote
footprint AssemblyNote (Assembly Note)

## CMP-0077240-1
designator J?, comment FLE-108-01-G-DV-A  (value not drawn)
Receptacle, 1.27mm, 8x2, Gold, SMT; Manufacturer: Samtec; Pitch_mm: 1.27; Gender: Female; Cert_CSA: Y; Current_A: 2A; CT: True; Row_Count: 2; CompType: Socket Strip; CNHeader: False
footprint Samtec_FLE-108-01-x-DV-A (Receptacle, 1.27mm, 8x2, SMT)
pins: 1, 2, 3, 4, 5, 6, 7, 8, 9, 10, 11, 12, 13, 14, 15, 16

## CMP-0077941-1
designator Q?, comment DMT3020LFDB-13
MOSFET, 2-CH, N-CH, 30 V, 7.7 A, AEC-Q101, U-DFN2020-6; PartNumber: DMT3020LFDB-7; Manufacturer: Diodes Inc.; Alternate Manufacturer: None; ChType: N; SizeAreaWB_mm2: 9; SizeArea_mm2: 4; IdsMax_A: 7.7A; AEC Qualified: Y; VdsMax_V: 30V; Rdson45_ohm: 0.032; Vgs_V: 20V; AEC Category: Q101; Value: 30V; SizeZ_mm: 0.575; SizeY_mm: 2; Value2: ? nC; U/M: EA; Value1: 0.032 ohm
footprint U-DFN2020-6_B (SMD, 6-Leads, Body 2x2mm, Pitch 0.65mm)
part A pins: 1 S1, 2 G1, 6 D1, 7 D1
part B pins: 3 D2, 4 S2, 5 G2, 8 D2

## CMP-0077948-2
designator D?, comment B540CQ-13-F
Diode, Schottky, 40 V, 5 A, AEC-Q101, SMC; Manufacturer: Diodes Inc.; AEC Category: Q101; SizeAreaWB_mm2: 83.2686; SizeX_mm: 8.13; Vf_V: 550mV; TJmax_C: 150°C; RJC_CperW: 10; Vr_V: 40V; SizeZ_mm: 2.6; AEC Qualified: Y; Value1: 5A; Value: 40V; Value2: 0.55V; SizeArea_mm2: 50.5686; SizeY_mm: 6.22
footprint SMC (Molded Diode, 2-Leads, Body 6.9x5.8mm, IPC Medium Density, based on OnSemi component dimensions and land patterns)
pins: 1 K, 2 A

## CMP-0078193-1
designator R?, comment ValueDisplayed: 1.0k  (hidden comment: ERJ-2GEJ102X)
RES, 1.0 k, 5%, 0.1 W, AEC-Q200 Grade 0, 0402; Manufacturer: Panasonic; Value_Code: 1k00; SizeArea_mm2: 0.5; AEC Qualified: Y; AEC Category: Q200; Res_ohm: 1k; Value: 1.0k; SizeZ_mm: 0.6; Green_REACh: Passed; EIA_Code: E24; TempCo: 200 ppm/C; AEC Grade: 0; Power_W: 100mW; VDC_V: 50V; Value2: 0.1W; Green_Lifecycle: Active; U/M: EA; CompType: Resistor; SizeX_mm: 1
footprint 0402 (0402 from SM-752 data)
footprint 0402M (0402 from SM-752 data)
footprint 0402L (0402 from SM-752 data)
footprint 0402S (Based on C0402S footprint from PADS legacy)
pins: 1, 2

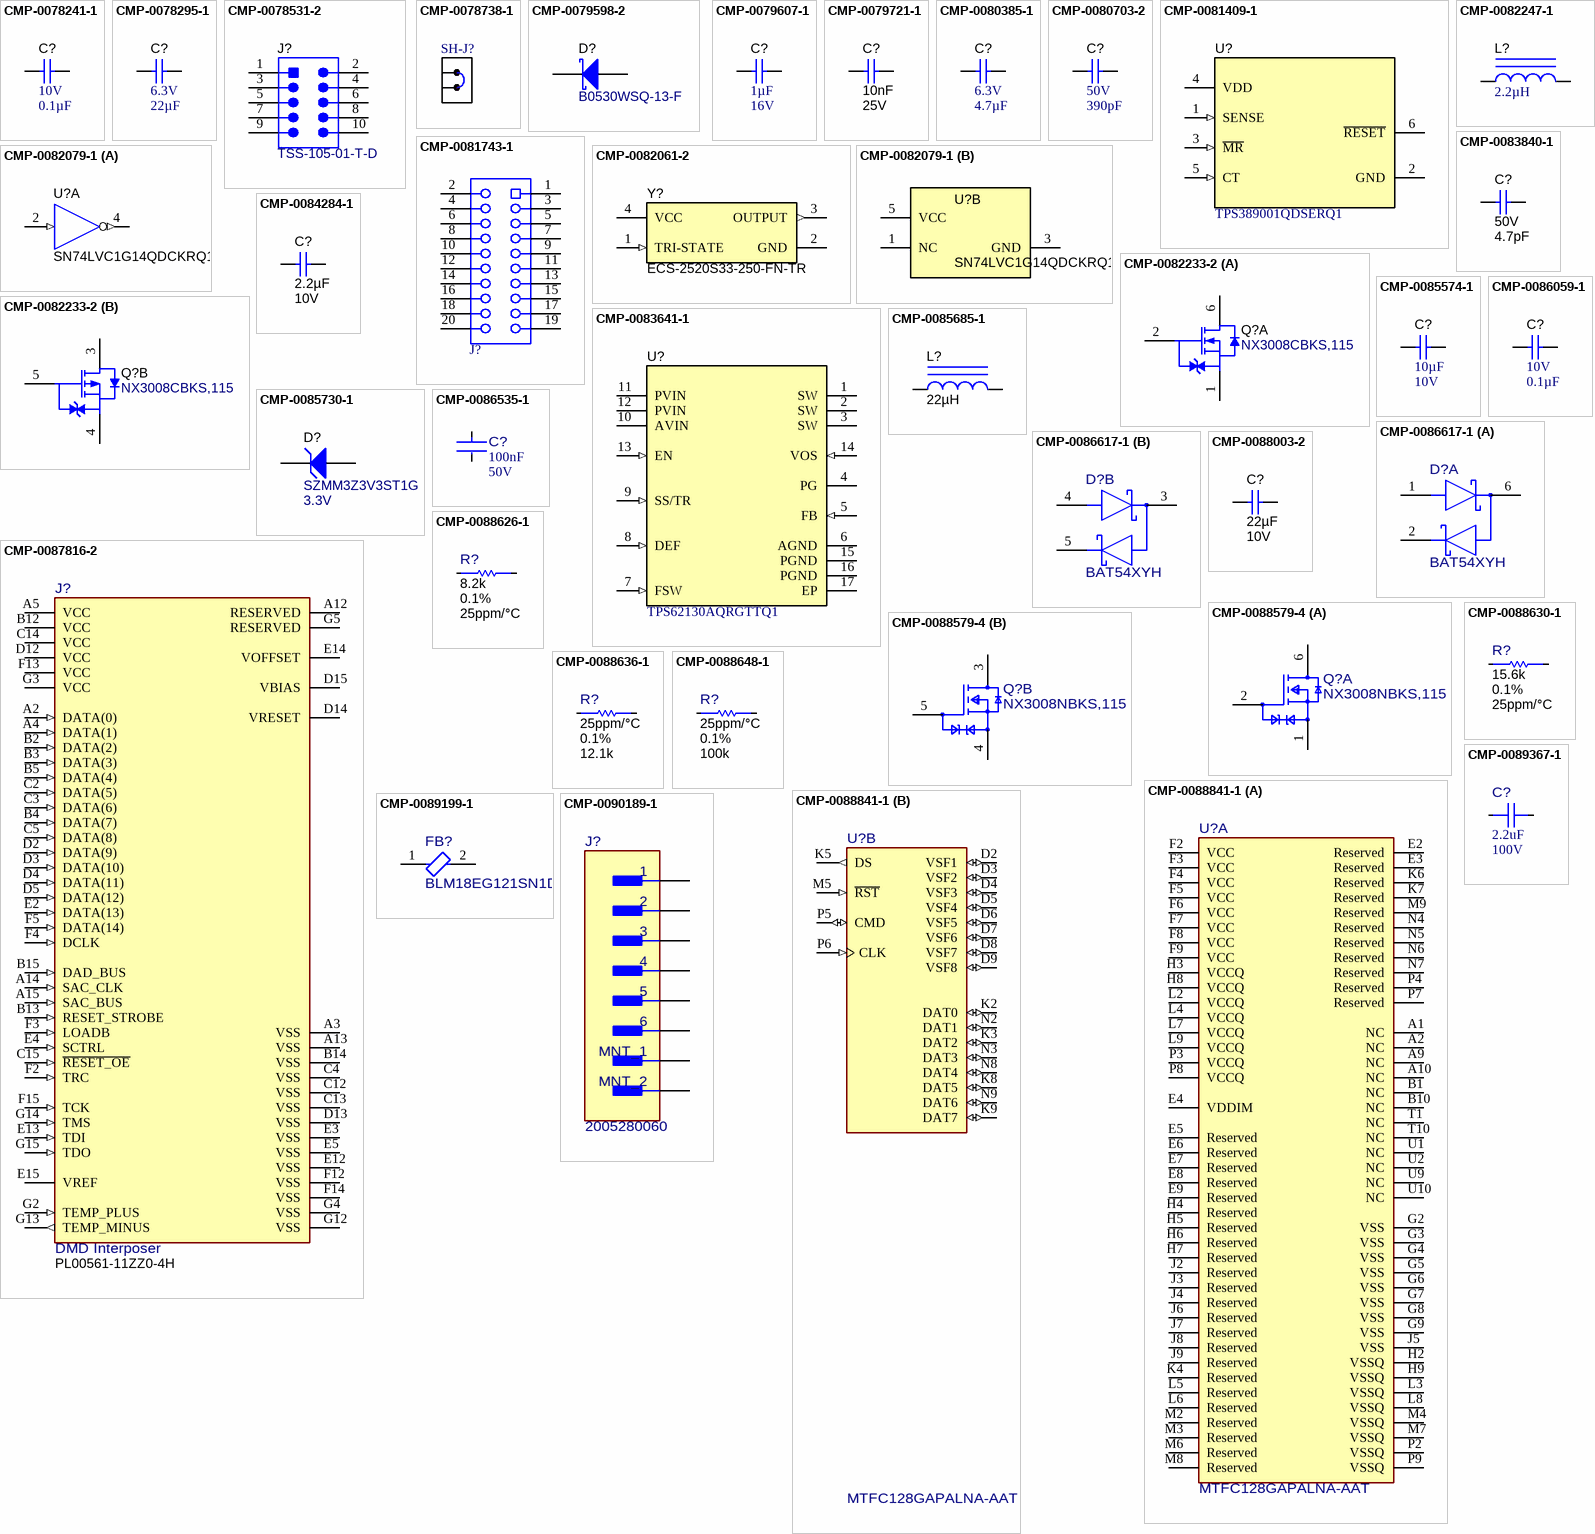
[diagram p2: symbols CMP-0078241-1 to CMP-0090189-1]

## CMP-0078241-1
designator C?, comment VDC_V: 10V  ValueDisplayed: 0.1µF  (hidden comment: C0402C104K8RACTU)
CAP, CERM, 0.1 µF, 10 V,+/- 10%, X7R, 0402; Manufacturer: Kemet; TaMin_C: -55°C; Polarized: N; SizeAreaWB_mm2: 3; U/M: EA; Value: 0.1uF; TaMax_C: 125°C; SizeZ_mm: 0.6; SizeX_mm: 1; SizeY_mm: 0.5; Cap_Case: 0402; CompType: Capacitor; Cap_F: 100nF; AEC Category: Q200
footprint 0402 (0402 from SM-752 data)
footprint 0402M (0402 from SM-752 data)
footprint 0402L (0402 from SM-752 data)
footprint 0402S (Based on C0402S footprint from PADS legacy)
pins: 1, 2

## CMP-0078295-1
designator C?, comment VDC_V: 6.3V  ValueDisplayed: 22µF  (hidden comment: GRM186R60J226ME15D)
CAP, CERM, 22 µF, 6.3 V,+/- 20%, X5R, 0603; Manufacturer: MuRata; TaMin_C: -55°C; Polarized: N; SizeAreaWB_mm2: 4.68; U/M: EA; Value: 22uF; TaMax_C: 85°C; SizeZ_mm: 1; SizeX_mm: 1.6; SizeY_mm: 0.8; Cap_Case: 0603; SizeArea_mm2: 1.28; CompType: Capacitor; AEC Category: Q200
footprint 0603 (0603 from SM-752 data)
footprint 0603M (0603 from SM-752 data)
footprint 0603L (0603 from SM-752 data)
footprint 0603_HV (Ernesto recommended land pattern.  26 mil between pads.)
footprint 0603S
pins: 1, 2

## CMP-0078531-2
designator J?, comment TSS-105-01-T-D
Header(shrouded), 2.54mm, 5x2, Tin, TH; Manufacturer: Samtec; Pitch_mm: 2.54; Gender: Male; Cert_UL: Y; Voltage_V: 1kV; Current_A: 3A; Row_Count: 2
footprint Samtec_TSS-105-01-x-D (Header(shrouded), 2.54mm, 5x2, TH)
pins: 1, 2, 3, 4, 5, 6, 7, 8, 9, 10
1 alternate drawing of the same symbol

## CMP-0078738-1
designator SH-J?, comment M7582-05  (value not drawn)
Single Operation 2.54mm Pitch Open Top Jumper Socket; Manufacturer: Harwin; CompType: Shunt
footprint Harwin_M7582-05 (Single Operation 2.54mm Pitch Open Top Jumper Socket)

## CMP-0079598-2
designator D?, comment B0530WSQ-13-F
Diode, Schottky, 30 V, 0.5 A, AEC-Q101, SOD-323; Manufacturer: Diodes Inc.; SizeAreaWB_mm2: 8.695; Vr_V: 30V; SizeArea_mm2: 3.645; AEC Qualified: Y; TJmax_C: 125°C; AEC Category: Q101; Value: 30V; SizeZ_mm: 1; Io_A: 500mA; Vf_V: 400mV; SizeY_mm: 1.35; Value2: 0.4V; Value1: 0.5A; SizeX_mm: 2.7
footprint SOD-323 (NXP recommended land pattern)
pins: 1 K, 2 A

## CMP-0079607-1
designator C?, comment Cap_F: 1µF  VDC_V: 16V  (hidden comment: CGA3E1X7R1C105K080AC)
CAP, CERM, 1 µF, 16 V,+/- 10%, X7R, AEC-Q200 Grade 1, 0603; Manufacturer: TDK; TaMin_C: -55°C; Polarized: N; SizeAreaWB_mm2: 4.68; U/M: EA; Value: 1uF; TaMax_C: 125°C; SizeZ_mm: 1; SizeX_mm: 1.6; SizeY_mm: 0.8; Cap_Case: 0603; SizeArea_mm2: 1.28; CompType: Capacitor; AEC Qualified: Y; AEC Category: Q200
footprint 0603 (0603 from SM-752 data)
footprint 0603M (0603 from SM-752 data)
footprint 0603L (0603 from SM-752 data)
footprint 0603_HV (Ernesto recommended land pattern.  26 mil between pads.)
footprint 0603S
pins: 1, 2

## CMP-0079721-1
designator C?, comment Cap_F: 10nF  VDC_V: 25V  (hidden comment: SR0603X7R103K1NT95(F)#M123A)
CAP, CERM, 0.01 µF, 25 V,+/- 10%, X7R, 0603; Manufacturer: Presidio Components; TaMin_C: -55°C; Polarized: N; SizeAreaWB_mm2: 4.68; U/M: EA; Value: 0.01uF; TaMax_C: 125°C; SizeZ_mm: 1; SizeX_mm: 1.6; SizeY_mm: 0.8; Cap_Case: 0603; SizeArea_mm2: 1.28; CompType: Capacitor; AEC Category: Q200; ValueDisplayed: 0.01µF
footprint 0603 (0603 from SM-752 data)
footprint 0603M (0603 from SM-752 data)
footprint 0603L (0603 from SM-752 data)
footprint 0603_HV (Ernesto recommended land pattern.  26 mil between pads.)
footprint 0603S
pins: 1, 2

## CMP-0080385-1
designator C?, comment VDC_V: 6.3V  ValueDisplayed: 4.7µF  (hidden comment: GRM155R60J475ME47J)
CAP, CERM, 4.7 µF,  VAC/6.3 VDC,+/- 20%, X5R, 0402; Manufacturer: MuRata; TaMin_C: -55°C; ESR_ohm: 1m; Polarized: N; SizeAreaWB_mm2: 3; Value1: 0.001 ohm; U/M: EA; Value: 4.7uF; TaMax_C: 85°C; SizeZ_mm: 0.6; SizeX_mm: 1; SizeY_mm: 0.5; Cap_Case: 0402; CompType: Capacitor; AEC Category: Q200
footprint 0402 (0402 from SM-752 data)
footprint 0402M (0402 from SM-752 data)
footprint 0402L (0402 from SM-752 data)
footprint 0402S (Based on C0402S footprint from PADS legacy)
pins: 1, 2

## CMP-0080703-2
designator C?, comment VDC_V: 50V  ValueDisplayed: 390pF  (hidden comment: GCM155R71H391KA37D)
CAP, CERM, 390 pF, 50 V,+/- 10%, X7R, AEC-Q200 Grade 1, 0402; Manufacturer: MuRata; Cap_Case: 0402; CompType: Capacitor; SizeX_mm: 1; SizeZ_mm: 0.6; SizeY_mm: 0.5; AEC Qualified: Y; Value: 390pF; Polarized: N; AEC Category: Q200; TaMax_C: 125°C; TaMin_C: -55°C; SizeAreaWB_mm2: 3; U/M: EA
footprint 0402 (0402 from SM-752 data)
footprint 0402M (0402 from SM-752 data)
footprint 0402L (0402 from SM-752 data)
footprint 0402S (Based on C0402S footprint from PADS legacy)
pins: 1, 2

## CMP-0081409-1
designator U?, comment TPS389001QDSERQ1
Automotive Low-Quiescent-Current 1% Accurate Supervisor With Programmable Delay, DSE0006A (WSON-6); Alternate Manufacturer: Texas Instruments; SizeAreaWB_mm2: 6.25; SizeZ_mm: 0.8; SizeX_mm: 1.5; SizeArea_mm2: 2.25; CompType: IC; AEC Qualified: Y; AEC Category: Q200
footprint DSE0006A (TI recommended land pattern)
pins: 1 SENSE (in), 2 GND (power), 3 ~{MR} (in), 4 VDD (power), 5 CT (in), 6 ~{RESET} (oc)

## CMP-0081743-1
designator J?, comment RSM-110-02-L-D  (value not drawn)
Receptacle, 1.27mm, 10x2, Gold with Tin tail, SMT; Manufacturer: Samtec; Pitch_mm: 1.27; Gender: Female; Cert_UL: Y; Current_A: 3.1A; RowSpacing_mm: 2.54; Row_Count: 2; CompType: Socket Strip
footprint Samtec_RSM-110-02-x-D (Receptacle, 1.27mm, 10x2, SMT)
pins: 1, 2, 3, 4, 5, 6, 7, 8, 9, 10, 11, 12, 13, 14, 15, 16, 17, 18, 19, 20

## CMP-0082061-2
designator Y?, comment ECS-2520S33-250-FN-TR
Oscillator, 25 MHz, 15 pF, SMD; Manufacturer: ECS Inc.; SizeAreaWB_mm2: 10.5; Frequency Stability: 10 ppm; SizeY_mm: 2.5; SizeZ_mm: 1; AEC Category: Q200; TaMax_C: 85°C; Load Capacitance: 15 pF; AEC Qualified: N; SizeX_mm: 2; TaMin_C: -40°C; Frequency_Fixed: 25MHz; SizeArea_mm2: 5
footprint ECS_ECS-2520S (SMD, 4-Leads, Body 2x2.5mm)
pins: 1 TRI-STATE (in), 2 GND (power), 3 OUTPUT (out), 4 VCC (power)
